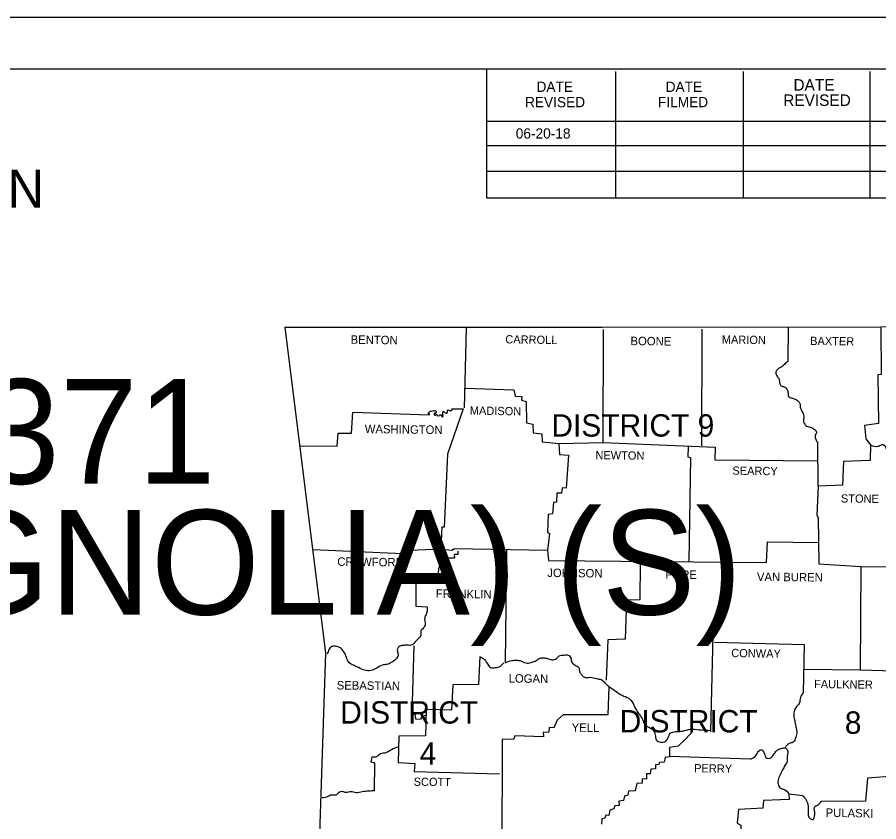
# Model space of a CAD drawing. Extents: x 61396 to 64680, y 55472 to 57605.
# Drawn here: x 63452 to 64111, y 56991 to 57605 of the extents above; entities that cross this region are included whole.
import ezdxf

# ---------------------------------------------------------------- set-up
doc = ezdxf.new("R2010")
doc.units = 0
doc.layers.add('Default', color=7, linetype='Continuous')
doc.layers.add('R_No Plot', color=7, linetype='Continuous')

msp = doc.modelspace()

# ---------------------------------------------------------------- linework, layer by layer
at = {"layer": 'Default'}
for p, q in [((61471.8, 57566.01), (64633.61, 57566.01)), ((63810.98, 57467.33), (63810.98, 57566.01)), ((63909.66, 57467.33), (63909.66, 57564.06)), ((64007.36, 57467.33), (64007.36, 57564.06)), ((64104.08, 57467.33), (64104.08, 57564.06)), ((63810.98, 57525.95), (64202.76, 57525.95)), ((63810.98, 57507.39), (64202.76, 57507.39)), ((63810.98, 57467.33), (63810.98, 57487.85)), ((63810.98, 57487.85), (64202.76, 57487.85)), ((64633.61, 57467.33), (63810.98, 57467.33))]:
    msp.add_line(p, q, dxfattribs=at)
for points in [[(63656.74, 57368.71), (63899.29, 57368.56), (64112.14, 57369.01), (64363.24, 57372.91), (64479.64, 57375.61)], [(63656.74, 57368.71), (63687.79, 57119.41), (63674.29, 56712.46)], [(63795.19, 57367.81), (63793.84, 57307.06)], [(63794.89, 57321.91), (63831.79, 57320.71), (63832.69, 57315.91), (63837.79, 57315.76), (63837.64, 57312.76), (63841.24, 57311.86), (63841.54, 57295.51), (63846.19, 57294.46), (63846.49, 57288.01), (63853.09, 57287.11), (63853.39, 57281.11), (63866.44, 57279.76), (63900.04, 57280.51), (63900.34, 57366.76)], [(63975.49, 57367.06), (63975.04, 57277.96)], [(64041.49, 57368.11), (64041.19, 57342.46)], [(64112.14, 57368.11), (64112.44, 57332.41), (64109.89, 57332.26), (64110.34, 57294.91), (64099.84, 57293.41), (64100.74, 57283.36), (64104.34, 57278.71), (64104.04, 57266.86), (64083.64, 57266.11), (64082.89, 57247.81), (64064.29, 57247.21), (64063.39, 57225.01), (64064.44, 57223.21), (64064.89, 57187.81), (64096.99, 57185.71), (64096.54, 57106.66), (64122.04, 57105.91), (64122.04, 57025.51), (64101.94, 57024.01), (64100.44, 57006.31), (64066.69, 57006.16)], [(63784.14, 57306.25), (63793.09, 57306.31), (63780.94, 57271.51), (63778.54, 57215.86), (63776.74, 57215.71), (63775.84, 57198.91), (63784.69, 57198.16), (63786.04, 57199.51), (63857.59, 57198.16), (63858.34, 57190.21)], [(63668.59, 57277.96), (63696.64, 57277.81), (63697.39, 57287.71), (63707.74, 57287.71), (63708.64, 57303.76), (63767.14, 57301.66)], [(63866.14, 57279.46), (63866.74, 57271.36), (63873.64, 57270.91), (63871.84, 57245.71), (63868.69, 57245.86), (63868.09, 57241.81), (63864.49, 57241.81), (63864.34, 57234.91), (63862.09, 57234.76), (63861.34, 57225.91), (63858.04, 57225.46), (63857.59, 57211.96), (63859.09, 57210.91), (63857.59, 57198.16)], [(63900.04, 57280.51), (63985.54, 57276.91), (63985.39, 57267.16), (64063.84, 57266.56)], [(64064.29, 57247.21), (64064.14, 57280.96)], [(63964.99, 57277.36), (63964.84, 57269.56), (63966.79, 57269.11), (63965.59, 57189.91)], [(63678.49, 57198.76), (63746.74, 57195.61), (63747.04, 57198.01), (63775.54, 57199.36)], [(63826.09, 57198.76), (63825.04, 57112.21)], [(63858.34, 57190.21), (64024.84, 57188.86), (64025.59, 57204.61), (64064.29, 57204.16)], [(63789.04, 57197.56), (63789.04, 57194.86), (63786.19, 57194.86), (63786.34, 57192.16), (63777.19, 57192.01), (63777.04, 57185.26), (63774.49, 57185.26), (63773.14, 57175.21), (63756.94, 57174.46), (63756.79, 57155.41), (63765.49, 57154.81)], [(63928.28, 57188.31), (63928.13, 57160.26), (63917.78, 57160.11), (63916.88, 57130.26), (63903.68, 57129.81), (63902.18, 57098.91)], [(63991.81, 57188.15), (63990.71, 57145.25), (63984.12, 57144.15), (63981.92, 57059.46)], [(64096.99, 57185.71), (64174.09, 57185.26), (64180.69, 57188.41), (64180.24, 57129.76), (64175.74, 57127.81), (64171.69, 57124.36), (64170.34, 57123.01), (64170.19, 57106.21), (64121.14, 57106.21)], [(63985.09, 57127.81), (64053.64, 57126.16), (64052.74, 57089.11)], [(63755.29, 57125.11), (63753.79, 57073.51), (63756.04, 57072.91), (63756.49, 57069.31), (63760.99, 57069.01), (63761.44, 57071.56), (63765.04, 57072.16)], [(63805.69, 57117.01), (63804.64, 57095.56), (63785.14, 57095.41), (63784.09, 57075.91), (63764.74, 57076.36), (63764.14, 57056.26), (63743.89, 57056.11), (63743.29, 57036.01), (63756.04, 57035.26), (63755.59, 57029.11), (63820.69, 57027.31)], [(64052.89, 57107.26), (64096.54, 57106.66)], [(63904.24, 57094.06), (63903.64, 57072.46), (63869.44, 57072.31), (63864.94, 57068.41), (63862.39, 57062.41), (63858.64, 57062.71), (63858.49, 57059.26), (63854.14, 57058.81), (63854.29, 57055.66), (63832.54, 57056.26), (63831.79, 57053.86), (63822.79, 57053.56), (63822.49, 56966.02)], [(63968.59, 57059.86), (63963.19, 57054.01), (63957.34, 57048.46), (63950.59, 57047.41), (63950.59, 57040.36), (63947.29, 57039.91), (63946.69, 57036.31), (63942.94, 57036.01), (63942.64, 57034.36), (63940.09, 57034.21), (63939.94, 57031.06), (63936.34, 57030.91), (63936.04, 57027.31), (63933.04, 57027.31), (63933.19, 57023.11), (63929.89, 57023.41), (63929.74, 57020.11), (63925.69, 57019.81), (63924.49, 57014.41), (63919.39, 57013.96), (63918.94, 57010.96), (63916.24, 57010.21), (63915.49, 57007.06), (63912.04, 57006.31), (63912.34, 57003.16), (63908.89, 57002.86), (63908.29, 57000.46), (63905.14, 56999.56), (63904.39, 56995.51), (63901.99, 56995.66), (63901.24, 56993.56), (63898.99, 56992.81), (63898.84, 56988.76)], [(63725.14, 57014.26), (63725.59, 57035.41), (63722.59, 57036.31), (63723.49, 57040.36)], [(64012.54, 57038.56), (63950.74, 57040.51)], [(64052.59, 57010.51), (64041.79, 57011.71), (64042.24, 57007.66), (64022.59, 57006.91), (64021.99, 57001.06), (64003.54, 57000.01), (64002.49, 56989.51), (64005.19, 56988.16), (64005.19, 56981.26)]]:
    msp.add_lwpolyline(points, dxfattribs=at)
for centre, radius, start, end in [((63770.96, 57296.05), 8.64, 111.58729, 117.31489), ((63769.69, 57299.02), 5.41, 102.75461, 110.65431), ((63774.1, 57274.2), 30.61, 96.79322, 100.55156), ((63771.06, 57301.86), 2.8, 89.33357, 102.09888), ((63771.07, 57302.23), 2.43, 66.56397, 89.33357), ((63771.6, 57303.45), 1.1, 32.46208, 66.56397), ((63777.87, 57303.25), 0.842, 84.28741, 120.97263), ((63777.9, 57303.56), 0.531, 25.12471, 84.28741), ((63781.14, 57303.88), 0.384, 131.93393, 211.14314), ((63782.09, 57304.38), 1.23, 165.76202, 190.35932), ((63781.83, 57304.71), 0.934, 152.9692, 181.54094), ((63781.58, 57302.97), 2.24, 70.65961, 104.90357), ((63783.59, 57307.74), 2.94, 244.39846, 264.96439), ((63783.28, 57307.58), 2.78, 271.1237, 284.04098), ((63783.9, 57305.11), 0.226, 284.04098, 330.46985), ((63783.16, 57306.26), 1.57, 306.54016, 333.86849), ((63783.58, 57305.4), 1.01, 9.51164, 55.94051), ((63766.48, 57302.74), 0.265, 156.04498, 216.86024), ((63766.6, 57302.69), 0.394, 125.54719, 156.04498), ((63767.01, 57303.14), 0.93, 216.86024, 248.19165), ((63773.41, 57297.5), 8.95, 135.87475, 141.93743), ((63766.73, 57302.44), 0.17, 248.19165, 347.15814), ((63767.06, 57302.36), 0.17, 39.79568, 167.15814), ((63767.06, 57301.99), 0.293, 286.23103, 356.42492), ((63766.64, 57302.02), 0.71, 356.42492, 39.79568), ((63771.78, 57302.11), 0.946, 132.41003, 167.33428), ((63773.55, 57302.81), 2.74, 190.48787, 208.87807), ((63771.52, 57302.63), 0.41, 68.14144, 155.54541), ((63771.49, 57301.89), 0.523, 229.26667, 280.08021), ((63771.67, 57301.85), 0.483, 259.69161, 298.81929), ((63771.82, 57303.4), 0.41, 248.09689, 311.88787), ((63771.73, 57301.75), 0.37, 298.81929, 356.0222), ((63770.86, 57304.47), 1.85, 311.88787, 335.77978), ((63772.47, 57301.7), 0.37, 110.86115, 176.0222), ((63772.39, 57301.88), 0.171, 67.37299, 110.86115), ((63771.42, 57299.55), 2.7, 56.68014, 67.37299), ((63772.23, 57303.85), 0.352, 335.77978, 32.46208), ((63772.3, 57300.89), 1.1, 31.41918, 56.68014), ((63774.11, 57301.62), 0.89, 190.50482, 239.80984), ((63773.89, 57302.19), 1.36, 260.46199, 312.72136), ((63775.47, 57300.49), 0.962, 103.76543, 132.98356), ((63776.61, 57295.81), 5.78, 94.97148, 103.76543), ((63776.15, 57301.19), 0.376, 60.00965, 94.97148), ((63776.15, 57301.2), 0.372, 333.5484, 60.00965), ((63776.91, 57301.04), 0.428, 181.13582, 232.59661), ((63778.77, 57301.69), 2.34, 205.00919, 220.22644), ((63777.1, 57300.16), 0.119, 169.06905, 214.07731), ((63777.05, 57300.67), 0.58, 265.23469, 310.24628), ((63778.19, 57303.17), 1.1, 133.16896, 186.72087), ((63779.48, 57303.32), 2.4, 186.725, 211.11856), ((63773.87, 57300.86), 3.76, 356.18726, 18.9181), ((63777.06, 57300.65), 0.558, 310.24628, 356.18726), ((63778.74, 57304.06), 0.453, 217.10299, 260.49463), ((63786, 57313.73), 12.49, 234.04327, 240.90113), ((63780.02, 57303.17), 0.37, 254.83999, 285.58456), ((63780.27, 57303.4), 0.607, 255.97878, 27.03998)]:
    msp.add_arc(centre, radius, start, end, dxfattribs=at)
for points in [[(64041.19, 57342.46), (64038.49, 57340.21), (64036.09, 57338.11), (64032.49, 57335.56), (64032.04, 57333.16), (64033.24, 57330.76), (64034.44, 57328.81), (64034.89, 57326.11), (64035.94, 57323.86), (64038.49, 57322.96), (64040.59, 57321.01), (64041.34, 57318.31), (64041.64, 57315.76), (64044.04, 57314.56), (64046.74, 57313.66), (64049.29, 57311.86), (64050.49, 57309.61), (64050.79, 57306.76), (64051.84, 57304.51), (64053.04, 57301.81), (64053.34, 57299.56), (64053.04, 57297.31), (64053.64, 57295.21), (64055.59, 57293.11), (64059.04, 57292.06), (64061.44, 57290.56), (64063.09, 57288.46), (64062.04, 57285.91), (64062.19, 57283.66), (64063.54, 57280.96)], [(64104.34, 57278.71), (64110.34, 57277.66), (64113.94, 57279.01), (64116.49, 57275.11), (64117.84, 57272.11), (64120.09, 57267.76), (64123.69, 57266.41), (64126.39, 57264.01), (64126.39, 57261.46), (64123.99, 57259.06), (64122.19, 57256.66), (64122.79, 57253.81), (64123.39, 57249.91), (64123.39, 57246.16), (64122.49, 57242.71), (64121.74, 57239.56), (64122.49, 57236.86), (64125.34, 57237.31), (64128.34, 57239.56), (64131.49, 57239.56), (64134.49, 57237.91), (64137.64, 57235.06), (64140.79, 57235.66), (64143.34, 57236.41), (64146.94, 57237.46), (64149.49, 57236.11), (64151.74, 57234.31), (64154.44, 57231.46), (64156.99, 57229.66), (64160.29, 57228.01), (64164.34, 57226.96), (64168.09, 57224.41), (64168.69, 57220.06), (64168.54, 57216.31), (64168.24, 57211.66), (64167.94, 57206.56), (64168.39, 57201.61), (64170.04, 57198.31), (64172.14, 57194.41), (64172.74, 57190.81), (64172.59, 57185.11)], [(63765.49, 57154.81), (63765.49, 57151.66), (63764.29, 57148.36), (63763.54, 57145.51), (63763.99, 57141.76), (63762.64, 57138.76), (63760.69, 57136.36), (63760.69, 57133.36), (63758.44, 57130.21), (63756.04, 57127.81), (63753.94, 57125.86), (63750.19, 57125.56), (63747.04, 57125.41), (63743.89, 57124.36), (63742.69, 57122.11), (63743.29, 57118.66), (63742.09, 57115.36), (63738.94, 57112.81), (63735.49, 57111.16), (63731.89, 57110.56), (63726.94, 57108.16), (63722.44, 57106.21), (63717.64, 57106.51), (63713.14, 57108.46), (63709.09, 57110.26), (63705.94, 57112.06), (63703.39, 57117.61), (63701.74, 57120.61), (63698.89, 57123.61), (63695.44, 57124.81), (63692.59, 57124.51), (63689.14, 57118.66)], [(63805.69, 57117.01), (63808.99, 57114.91), (63811.54, 57111.46), (63813.79, 57108.61), (63817.54, 57108.46), (63820.54, 57109.06), (63823.99, 57112.06)], [(63825.04, 57112.21), (63829.99, 57113.86), (63833.59, 57114.16), (63837.19, 57113.56), (63840.94, 57112.06), (63844.99, 57112.36), (63847.99, 57113.41), (63850.99, 57115.36), (63854.29, 57115.96), (63857.44, 57115.36), (63860.74, 57114.46), (63864.34, 57115.51), (63866.44, 57117.46), (63870.04, 57118.06), (63873.19, 57118.06), (63875.44, 57115.51), (63875.89, 57112.81), (63878.74, 57110.26), (63881.29, 57108.61), (63882.04, 57105.46), (63883.39, 57103.21), (63884.74, 57101.71), (63886.69, 57100.81), (63889.99, 57101.11), (63895.09, 57100.06), (63898.39, 57099.31), (63901.39, 57096.76), (63904.24, 57094.06)], [(63904.24, 57094.06), (63909.49, 57090.46), (63914.44, 57087.31), (63919.54, 57085.06), (63922.39, 57081.76), (63924.94, 57076.66), (63927.04, 57073.51), (63929.74, 57069.61), (63931.69, 57065.26), (63934.84, 57062.86), (63938.14, 57060.76), (63939.79, 57057.01), (63940.54, 57053.26), (63944.14, 57051.46), (63947.59, 57052.21), (63949.54, 57054.46), (63951.34, 57058.36), (63955.39, 57059.56), (63960.64, 57060.01), (63966.64, 57061.36), (63973.24, 57061.06), (63982.54, 57060.46)], [(64052.74, 57089.11), (64050.79, 57085.66), (64049.89, 57081.16), (64047.49, 57078.31), (64045.99, 57075.01), (64045.84, 57070.66), (64046.59, 57066.76), (64047.34, 57063.01), (64047.94, 57059.56), (64047.19, 57055.21), (64045.24, 57051.46), (64042.24, 57050.41), (64039.39, 57047.86)], [(63723.49, 57040.36), (63726.79, 57040.66), (63729.94, 57042.76), (63734.14, 57043.66), (63738.34, 57045.91), (63743.59, 57048.31)], [(64012.54, 57038.56), (64016.29, 57040.66), (64018.24, 57043.81), (64020.64, 57045.76), (64023.04, 57043.06), (64025.14, 57039.16), (64027.39, 57039.16), (64030.24, 57041.86), (64032.04, 57044.26), (64034.29, 57046.06), (64036.69, 57046.81), (64039.24, 57047.11), (64041.19, 57044.26), (64040.59, 57039.76), (64040.59, 57036.76), (64038.94, 57033.61), (64037.14, 57030.31), (64035.19, 57026.56), (64033.69, 57022.51), (64033.99, 57018.61), (64036.09, 57016.06), (64038.49, 57015.31), (64041.79, 57012.01)], [(63725.14, 57014.26), (63720.79, 57014.11), (63715.84, 57013.51), (63711.34, 57012.91), (63707.29, 57013.66), (63703.54, 57013.06), (63700.99, 57013.66), (63697.84, 57012.91), (63696.04, 57011.11), (63692.29, 57011.11), (63689.59, 57009.91), (63685.24, 57008.86)], [(64052.59, 57010.51), (64055.14, 57007.21), (64056.64, 57002.71), (64056.64, 56997.61), (64057.84, 56993.41), (64060.24, 56992.51), (64061.74, 56996.11), (64061.44, 56999.71), (64061.44, 57001.81), (64063.99, 57003.61), (64066.69, 57006.16)]]:
    msp.add_spline(points, degree=3, dxfattribs=at)
at = {"layer": 'R_No Plot'}
msp.add_lwpolyline([(61396.28, 57605.48), (64679.67, 57605.48), (64679.67, 55472.15), (61396.28, 55472.15)], close=True, dxfattribs=at)

# ---------------------------------------------------------------- texts
at = {"layer": 'Default'}
for s, height, p in [('DATE', 7.82, (63849.08, 57548.42)), ('DATE', 7.82, (63947.76, 57548.42)), ('DATE', 8.793, (64045.46, 57549.4)), ('REVISED', 7.82, (63840.29, 57536.7)), ('FILMED', 7.82, (63941.9, 57536.7)), ('REVISED', 8.793, (64037.64, 57537.68)), ('06-20-18', 7.82, (63833.21, 57512.77)), ('ARKANSAS DEPARTMENT OF TRANSPORTATION', 28.9998, (62550.59, 57459.92)), ('HWYS. 82B & 371 ', 80.0002, (62723.64, 57248.95)), ('DISTRICT 9', 17.1, (63860.44, 57285.01)), ('(SEL. SECS.) (MAGNOLIA) (S)', 80.0002, (62514.19, 57148.95)), ('DISTRICT', 17.1, (63699.04, 57065.71)), ('DISTRICT', 17.1, (63912.64, 57058.96)), ('8', 17.1, (64084.69, 57057.91)), ('4', 17.1, (63759.79, 57034.21))]:
    msp.add_text(s, height=height, dxfattribs=at).set_placement(p)
for s, height, rotation, p in [('BENTON', 6.451, 359.25271, (63706.99, 57355.96)), ('CARROLL', 6.301, 359.14808, (63825.19, 57356.26)), ('BOONE', 6.451, 359.40007, (63920.89, 57354.91)), ('MARION', 6.301, 359.18542, (63990.64, 57356.11)), ('BAXTER', 6.301, 359.25594, (64058.14, 57355.06)), ('MADISON', 6.301, 359.09062, (63798.04, 57301.81)), ('WASHINGTON', 6.449, 359.23201, (63717.79, 57287.71)), ('NEWTON', 6.301, 359.2717, (63894.04, 57267.76)), ('SEARCY', 6.299, 359.25271, (63998.74, 57255.91)), ('STONE', 6.299, 359.40007, (64081.69, 57234.61)), ('CRAWFORD', 6.449, 359.27706, (63696.79, 57186.31)), ('JOHNSON', 6.451, 359.3514, (63857.29, 57177.76)), ('POPE', 6.451, 359.61547, (63947.59, 57176.41)), ('VAN BUREN', 6.451, 359.35078, (64017.49, 57174.76)), ('FRANKLIN', 6.451, 359.18154, (63772.09, 57161.86)), ('CONWAY', 6.299, 359.03714, (63997.84, 57116.56)), ('LOGAN', 6.451, 359.39691, (63827.74, 57097.06)), ('SEBASTIAN', 6.449, 359.28159, (63696.34, 57091.81)), ('FAULKNER', 6.301, 359.24862, (64061.14, 57092.86)), ('YELL', 6.451, 359.19871, (63875.89, 57059.56)), ('PERRY', 6.301, 359.08578, (63969.49, 57028.51)), ('SCOTT', 6.301, 359.40628, (63755.14, 57018.16)), ('PULASKI', 6.451, 359.05305, (64069.99, 56994.46))]:
    msp.add_text(s, height=height, rotation=rotation, dxfattribs=at).set_placement(p)

doc.saveas('drawing.dxf')
